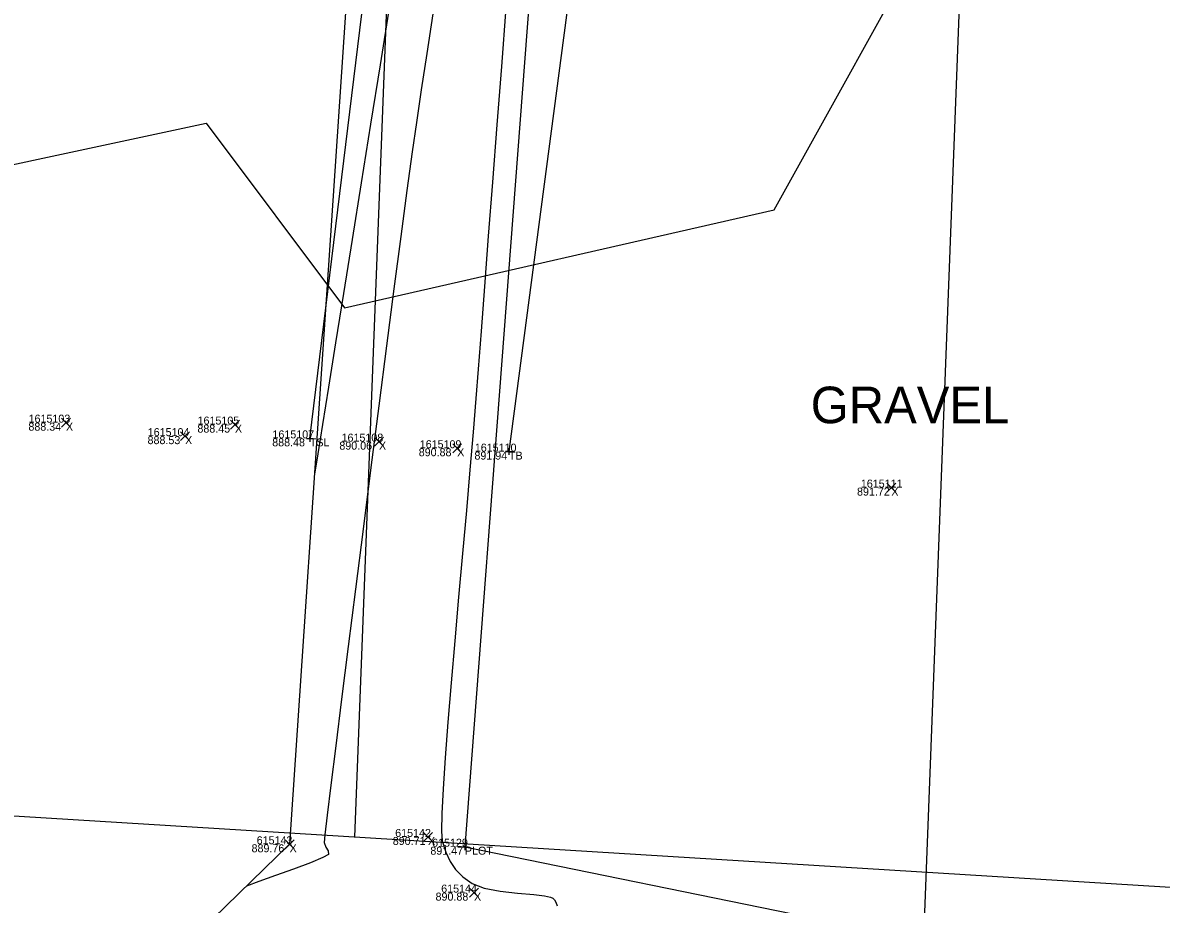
# Model space of a CAD drawing. Extents: x 1957117 to 1971063, y 701601 to 715861.
# Drawn here: x 1962659.74 to 1962709.51, y 702036.06 to 702074.62 of the extents above; entities that cross this region are included whole.
import ezdxf

# ---------------------------------------------------------------- set-up
doc = ezdxf.new("R2010")
doc.units = 0
for name, color, linetype in [('AP_X_Lights', 7, 'Continuous'), ('DT_X_Break_Line', 7, 'Continuous'), ('DT_X_Contour_Major', 7, 'Continuous'), ('DT_X_Contour_Minor', 7, 'Continuous'), ('DT_X_TIN_Hull', 7, 'Continuous'), ('GE_X_CL_20', 7, 'Continuous'), ('PV_P_Drive', 7, 'Continuous'), ('PV_P_Shoulder', 7, 'Continuous'), ('PV_X_Bikeway', 7, 'Continuous'), ('RS_Raster1', 7, 'Continuous'), ('RW_X_Esmt_RR', 7, 'Continuous'), ('RW_X_Fee_RW', 7, 'Continuous'), ('SC_Scratch1', 7, 'Continuous'), ('VG_X_Tree_Line_Rt', 7, 'Continuous')]:
    doc.layers.add(name, color=color, linetype=linetype)

msp = doc.modelspace()

# ---------------------------------------------------------------- linework, layer by layer
at = {"layer": 'AP_X_Lights'}
for p, q in [((1962661.435, 702056.933), (1962661.823, 702057.323)), ((1962661.435, 702057.323), (1962661.823, 702056.933)), ((1962668.823, 702056.849), (1962669.211, 702057.239)), ((1962668.823, 702057.239), (1962669.211, 702056.849)), ((1962666.642, 702056.343), (1962667.03, 702056.733)), ((1962666.642, 702056.733), (1962667.03, 702056.343)), ((1962675.12, 702056.102), (1962675.508, 702056.492)), ((1962675.12, 702056.492), (1962675.508, 702056.102)), ((1962678.538, 702055.814), (1962678.926, 702056.204)), ((1962678.538, 702056.204), (1962678.926, 702055.814)), ((1962697.517, 702054.091), (1962697.905, 702054.481)), ((1962697.517, 702054.481), (1962697.905, 702054.091)), ((1962677.263, 702038.808), (1962677.651, 702039.198)), ((1962677.263, 702039.198), (1962677.651, 702038.808)), ((1962671.211, 702038.488), (1962671.599, 702038.878)), ((1962671.211, 702038.878), (1962671.599, 702038.488)), ((1962679.274, 702036.373), (1962679.662, 702036.763)), ((1962679.274, 702036.763), (1962679.662, 702036.373))]:
    msp.add_line(p, q, dxfattribs=at)
at = {"layer": 'DT_X_Break_Line'}
for points in [[(1962712.212, 702702.955), (1962716.271, 702654.75), (1962711.053, 702609.737), (1962713.646, 702554.428), (1962708.781, 702505.283), (1962707.233, 702455.469), (1962704.944, 702406.927), (1962695.192, 702355.079), (1962699.519, 702306.049), (1962692.358, 702256.103), (1962693.103, 702205.318), (1962697.09, 702154.707), (1962695.369, 702143.214), (1962687.557, 702105.709), (1962680.996, 702055.861)], [(1962672.291, 702056.441), (1962678.402, 702106.354), (1962662.847, 702156.902), (1962653.64, 702207.97), (1962682.578, 702256.2), (1962687.088, 702305.912), (1962688.383, 702356.115), (1962688.326, 702413.221), (1962687.321, 702456.746), (1962695.78, 702508.037), (1962696.797, 702556.263), (1962699.455, 702605.505), (1962702.117, 702657.987), (1962703.272, 702699.736)]]:
    msp.add_lwpolyline(points, dxfattribs=at)
at = {"layer": 'DT_X_Contour_Major'}
msp.add_lwpolyline([(1962677.67, 702075.007), (1962677.4, 702073.28), (1962677.156, 702071.683), (1962676.947, 702070.267), (1962676.766, 702068.979), (1962676.538, 702067.292), (1962676.269, 702065.271), (1962675.969, 702062.982), (1962675.645, 702060.492), (1962675.306, 702057.866), (1962674.961, 702055.172), (1962674.617, 702052.475), (1962674.283, 702049.842), (1962673.967, 702047.339), (1962673.678, 702045.032), (1962673.423, 702042.988), (1962673.212, 702041.273), (1962673.052, 702039.952), (1962672.952, 702039.094), (1962672.92, 702038.763), (1962672.995, 702038.556), (1962673.094, 702038.392), (1962673.102, 702038.238), (1962672.866, 702038.1), (1962672.317, 702037.874), (1962671.581, 702037.598), (1962670.785, 702037.31), (1962670.056, 702037.047), (1962669.519, 702036.848)], dxfattribs=at)
msp.add_lwpolyline([(1962677.67, 702075.007), (1962677.4, 702073.28), (1962677.156, 702071.683), (1962676.947, 702070.267), (1962676.766, 702068.979), (1962676.538, 702067.292), (1962676.269, 702065.271), (1962675.969, 702062.982), (1962675.645, 702060.492), (1962675.306, 702057.866), (1962674.961, 702055.172), (1962674.617, 702052.475), (1962674.283, 702049.842), (1962673.967, 702047.339), (1962673.678, 702045.032), (1962673.423, 702042.988), (1962673.212, 702041.273), (1962673.052, 702039.952), (1962672.952, 702039.094), (1962672.92, 702038.763), (1962672.995, 702038.556), (1962673.094, 702038.392), (1962673.102, 702038.238), (1962672.866, 702038.1), (1962672.317, 702037.874), (1962671.581, 702037.598), (1962670.785, 702037.31), (1962670.056, 702037.047), (1962669.519, 702036.848)], dxfattribs=at)
at = {"layer": 'DT_X_Contour_Minor'}
for points in [[(1962675.776, 702075.359), (1962675.363, 702072.788), (1962674.947, 702070.192), (1962674.535, 702067.624), (1962674.136, 702065.136), (1962673.759, 702062.782), (1962673.412, 702060.614), (1962673.102, 702058.686), (1962672.84, 702057.051), (1962672.633, 702055.761), (1962672.49, 702054.869)], [(1962675.776, 702075.359), (1962675.363, 702072.788), (1962674.947, 702070.192), (1962674.535, 702067.624), (1962674.136, 702065.136), (1962673.759, 702062.782), (1962673.412, 702060.614), (1962673.102, 702058.686), (1962672.84, 702057.051), (1962672.633, 702055.761), (1962672.49, 702054.869)], [(1962680.861, 702075.27), (1962680.663, 702072.709), (1962680.467, 702070.151), (1962680.275, 702067.655), (1962680.093, 702065.28), (1962679.925, 702063.085), (1962679.775, 702061.131), (1962679.648, 702059.475), (1962679.548, 702058.179), (1962679.431, 702056.717), (1962679.29, 702055.067), (1962679.134, 702053.279), (1962678.967, 702051.404), (1962678.797, 702049.491), (1962678.629, 702047.59), (1962678.471, 702045.751), (1962678.328, 702044.026), (1962678.208, 702042.463), (1962678.116, 702041.112), (1962678.06, 702040.025), (1962678.044, 702039.25), (1962678.076, 702038.839), (1962678.234, 702038.338), (1962678.42, 702037.927), (1962678.659, 702037.578), (1962678.974, 702037.265), (1962679.39, 702036.963), (1962679.91, 702036.757), (1962680.607, 702036.628), (1962681.369, 702036.548), (1962682.086, 702036.486), (1962682.554, 702036.429), (1962682.805, 702036.371), (1962682.912, 702036.322), (1962682.944, 702036.294), (1962682.98, 702036.248), (1962683.041, 702036.148), (1962683.105, 702035.983)], [(1962680.861, 702075.27), (1962680.663, 702072.709), (1962680.467, 702070.151), (1962680.275, 702067.655), (1962680.093, 702065.28), (1962679.925, 702063.085), (1962679.775, 702061.131), (1962679.648, 702059.475), (1962679.548, 702058.179), (1962679.431, 702056.717), (1962679.29, 702055.067), (1962679.134, 702053.279), (1962678.967, 702051.404), (1962678.797, 702049.491), (1962678.629, 702047.59), (1962678.471, 702045.751), (1962678.328, 702044.026), (1962678.208, 702042.463), (1962678.116, 702041.112), (1962678.06, 702040.025), (1962678.044, 702039.25), (1962678.076, 702038.839), (1962678.234, 702038.338), (1962678.42, 702037.927), (1962678.659, 702037.578), (1962678.974, 702037.265), (1962679.39, 702036.963), (1962679.91, 702036.757), (1962680.607, 702036.628), (1962681.369, 702036.548), (1962682.086, 702036.486), (1962682.554, 702036.429), (1962682.805, 702036.371), (1962682.912, 702036.322), (1962682.944, 702036.294), (1962682.98, 702036.248), (1962683.041, 702036.148), (1962683.105, 702035.983)]]:
    msp.add_lwpolyline(points, dxfattribs=at)
at = {"layer": 'DT_X_TIN_Hull'}
msp.add_lwpolyline([(1962657.931, 702308.011), (1962655.854, 702258.355), (1962653.64, 702207.97), (1962651.503, 702157.712), (1962649.771, 702107.746), (1962674.688, 702087.643), (1962671.405, 702038.683), (1962651.95, 702019.751), (1962598.276, 702023.522), (1962596.236, 701997.877), (1962651.443, 701993.881), (1962750.651, 701987.35), (1962803.275, 701984.672), (1962804.883, 701997.219), (1962805.914, 702009.441), (1962753.632, 702013.572), (1962730.2, 702029.616), (1962722.307, 702088.916), (1962751.157, 702101.248), (1962753.404, 702150.955), (1962757.576, 702251.621), (1962759.026, 702351.713)], dxfattribs=at)
at = {"layer": 'GE_X_CL_20'}
msp.add_lwpolyline([(1962741.373, 703141.619), (1962697.729, 701998.272)], dxfattribs=at)
at = {"layer": 'PV_P_Drive'}
for p, q in [((1962672.291, 702056.587), (1962672.291, 702056.295)), ((1962672.145, 702056.441), (1962672.437, 702056.441)), ((1962672.291, 702056.441), (1962672.291, 702056.441)), ((1962680.996, 702056.007), (1962680.996, 702055.715)), ((1962680.85, 702055.861), (1962681.142, 702055.861)), ((1962680.996, 702055.861), (1962680.996, 702055.861)), ((1962678.924, 702038.576), (1962679.216, 702038.576)), ((1962679.07, 702038.722), (1962679.07, 702038.43)), ((1962679.07, 702038.576), (1962679.07, 702038.576))]:
    msp.add_line(p, q, dxfattribs=at)
at = {"layer": 'PV_X_Bikeway'}
msp.add_lwpolyline([(1962713.167, 702029.519), (1962715.026, 702029.838), (1962713.685, 702031.456), (1962716.601, 702087.336), (1962682.889, 702088.807), (1962679.07, 702038.576), (1962694.764, 702035.361), (1962694.695, 702030.456), (1962696.191, 702030.089)], dxfattribs=at)
at = {"layer": 'RW_X_Esmt_RR'}
msp.add_lwpolyline([(1962674.265, 702039.003), (1962716.391, 703142.573)], dxfattribs=at)
at = {"layer": 'RW_X_Fee_RW'}
msp.add_line((1957995.287, 702327.157), (1968723.77, 701666.445), dxfattribs=at)
at = {"layer": 'VG_X_Tree_Line_Rt'}
msp.add_lwpolyline([(1962654.57, 702149.712), (1962660.569, 702142.56), (1962659.212, 702133.988), (1962654.978, 702118.048), (1962660.346, 702106.792), (1962660.346, 702106.792), (1962654.43, 702101.553), (1962652.311, 702066.915), (1962667.755, 702070.232), (1962673.804, 702062.151), (1962692.583, 702066.445), (1962699.739, 702079.35), (1962700.636, 702088.753), (1962713.933, 702088.72), (1962716.232, 702078.774), (1962721.334, 702073.125), (1962719.433, 702062.796), (1962718.435, 702051.422), (1962724.351, 702042.104), (1962737.296, 702036.111), (1962751.323, 702040.439)], dxfattribs=at)

# ---------------------------------------------------------------- texts
at = {"layer": 'DT_X_Break_Line'}
msp.add_text('GRAVEL', height=1.6, dxfattribs=at).set_placement((1962694.187, 702057.103))
at = {"layer": 'PV_P_Shoulder'}
for s, p in [('888.34', (1962659.987, 702056.778)), ('888.45', (1962667.375, 702056.694)), ('888.53', (1962665.196, 702056.188)), ('888.48', (1962670.646, 702056.091)), ('890.06', (1962673.581, 702055.947)), ('890.88', (1962677.051, 702055.659)), ('891.94', (1962679.486, 702055.511)), ('891.72', (1962696.212, 702053.936)), ('889.76', (1962669.743, 702038.333)), ('890.71', (1962675.916, 702038.653)), ('891.47', (1962677.56, 702038.226)), ('890.88', (1962677.787, 702036.218))]:
    msp.add_text(s, height=0.35, dxfattribs=at).set_placement(p)
at = {"layer": 'RS_Raster1'}
for s, p in [('1615103', (1962659.995, 702057.128)), ('1615105', (1962667.383, 702057.044)), ('1615104', (1962665.205, 702056.538)), ('1615107', (1962670.657, 702056.441)), ('1615108', (1962673.678, 702056.297)), ('1615109', (1962677.096, 702056.009)), ('1615110', (1962679.503, 702055.861)), ('1615111', (1962696.38, 702054.286)), ('615142', (1962676.022, 702039.003)), ('615143', (1962669.967, 702038.683)), ('615129', (1962677.637, 702038.576)), ('615144', (1962678.033, 702036.568))]:
    msp.add_text(s, height=0.35, dxfattribs=at).set_placement(p)
at = {"layer": 'SC_Scratch1'}
for s, p in [('X', (1962661.629, 702056.778)), ('X', (1962669.017, 702056.694)), ('X', (1962666.836, 702056.188)), ('TSL', (1962672.291, 702056.091)), ('X', (1962675.314, 702055.947)), ('X', (1962678.732, 702055.659)), ('TB', (1962680.996, 702055.511)), ('X', (1962697.711, 702053.936)), ('X', (1962671.405, 702038.333)), ('X', (1962677.457, 702038.653)), ('PLOT', (1962679.07, 702038.226)), ('X', (1962679.468, 702036.218))]:
    msp.add_text(s, height=0.35, dxfattribs=at).set_placement(p)

doc.saveas('drawing.dxf')
